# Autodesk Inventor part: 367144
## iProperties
Created: 2006-10
Part Number: 367144
Material: 8.8 vz
Description: Zylinderschraube
Vendor: Autodesk Inc.
Document SubType Name: Modeling
Standard: DIN 912
Designer: I.Baliuc
Standards Organization: DIN
Language: de-DE
Size Designation: M6 x 12
Categories: <MemberInstance Version="R10.0.0"><Categories><Category DisplayName="Schrauben" InternalName="e4da775c-781d-43d5-af7c-5136215cf5a6" Mnemonic="FSTN"><Category Di
Density: 7.85 g/cm^3
Abmessung: M6 x 12
Author: T.Messerschmitt
Comments: DIN 912 - M6 x 12
Revision Number: 367144
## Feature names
1. Körper [Revolution]
2. Loch [Extrusion]
3. Rundung1 [Fillet]
4. Fase1 [Chamfer]
